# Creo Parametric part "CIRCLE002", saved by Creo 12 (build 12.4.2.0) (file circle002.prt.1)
Units: Custom; MM, KILOGRAM, SECS

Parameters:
  PTC_WM_ITERATION = "0"
  PTC_WM_VERSION = "-.0"
  PTC_WM_LIFECYCLE_STATE = "In Work"
  PTC_WM_LIFECYCLE = "MO_CADDocument"
  PTC_WM_CREATED_BY = "Maximilian Roepper (Z0017RMS: MO)"
  PTC_WM_CREATED_ON = "18-Sep-26 11:36:42 AM"
  PTC_WM_MODIFIED_BY = "Maximilian Roepper (Z0017RMS: MO)"
  PTC_WM_MODIFIED_ON = "18-Sep-26 11:36:46 AM"
  PDMLINKNUMBER = "PDM000071454769"
  PTC_WM_NAME = "circle002.prt"
  PTC_WM_NUMBER = "PDM000071454769"

Other parameters: WEIGHT, WEIGHT_FACTOR, WEIGHT_ADD, _MASS_TEMP, _DIFF_TEMP, MC_ERRORS, SUPPLIER

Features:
  1. coordinate system
  2. datum plane "PRT_YZ"
  3. datum plane "PRT_XY"
  4. datum plane "PRT_XZ"
  5. coordinate system
  6. datum axis
  7. datum axis
  8. datum axis
  9. coordinate system
  10. imported feature
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
Other named items: PRT, SIEMENS_MO, DRW_VIEW_ORG, PRT_X, PRT_Y, PRT_Z, CS0, ROUGH_GROB

Layers: 00_STD_CSYS-KSYS, 01_STD_PLANES-EBENEN, 02_STD_AXES-ACHSEN, 03_STD_CSYS-KSYS, 24_IMPORT_FEAT-IMPORT_KE

Surfaces: 2 cylinder, 2 plane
